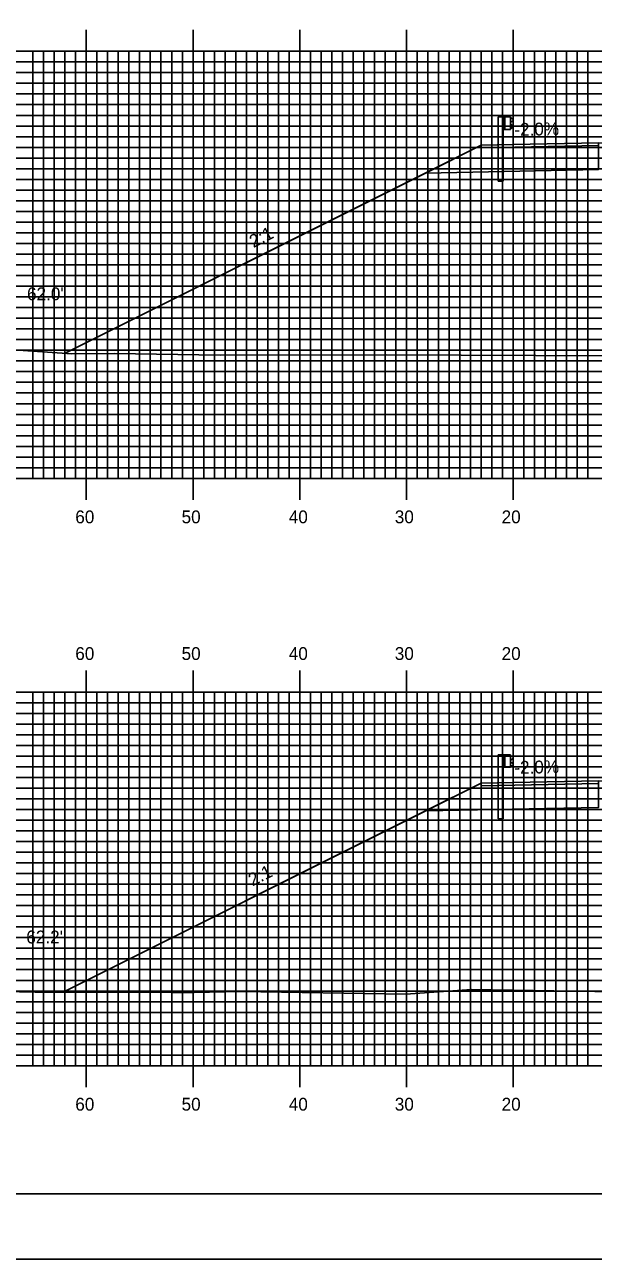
# Model space of a CAD drawing. Extents: x 1812161 to 1812504, y 442591 to 442811.
# Drawn here: x 1812260.7 to 1812313.9, y 442590.5 to 442706.2 of the extents above; entities that cross this region are included whole.
import ezdxf

# ---------------------------------------------------------------- set-up
doc = ezdxf.new("R2010")
doc.units = 0
for name, color, linetype in [('ANNOTATION', 7, 'Continuous'), ('BORDER', 7, 'Continuous'), ('D_Guardrail_Beam_Lt', 7, 'Continuous'), ('D_Roadway_Centerline', 7, 'Continuous'), ('D_Roadway_Edge_Shoulder', 7, 'Continuous'), ('D_Roadway_SlopeLines', 7, 'Continuous'), ('D_Roadway_SubGrade', 7, 'Continuous'), ('D_Text_Standard', 7, 'Continuous'), ('H_V ANNOTATION', 7, 'Continuous'), ('MAJOR', 7, 'Continuous'), ('MINOR', 7, 'Continuous'), ('PLOT BOUNDARY', 7, 'Continuous'), ('S_Roadway_Centerline', 7, 'Continuous')]:
    doc.layers.add(name, color=color, linetype=linetype)

msp = doc.modelspace()

# ---------------------------------------------------------------- linework, layer by layer
at = {"layer": 'BORDER'}
msp.add_lwpolyline([(1812176.83, 442596.67), (1812496.83, 442596.67), (1812496.83, 442806.67), (1812176.83, 442806.67)], close=True, dxfattribs=at)
at = {"layer": 'D_Guardrail_Beam_Lt'}
for p, q in [((1812305, 442697.52), (1812305, 442691.52)), ((1812305.47, 442697.52), (1812305, 442697.52)), ((1812306.16, 442697.52), (1812305.47, 442697.52)), ((1812305.47, 442697.52), (1812305.47, 442696.35)), ((1812305.53, 442697.52), (1812305.53, 442696.35)), ((1812305.64, 442697.52), (1812305.64, 442696.35)), ((1812306.16, 442696.35), (1812306.16, 442697.52)), ((1812306.16, 442697.44), (1812306.23, 442697.42)), ((1812306.39, 442697.17), (1812306.2, 442697.04)), ((1812306.25, 442697.41), (1812306.39, 442697.31)), ((1812305.47, 442696.35), (1812306.16, 442696.35)), ((1812305.49, 442691.52), (1812305.49, 442696.35)), ((1812306.16, 442696.97), (1812306.16, 442696.9)), ((1812306.23, 442696.45), (1812306.16, 442696.44)), ((1812306.2, 442696.84), (1812306.39, 442696.7)), ((1812306.39, 442696.56), (1812306.25, 442696.46)), ((1812305.49, 442691.52), (1812305, 442691.52)), ((1812305, 442637.78), (1812305, 442631.78)), ((1812305.47, 442637.78), (1812305, 442637.78)), ((1812306.16, 442637.78), (1812305.47, 442637.78)), ((1812305.47, 442637.78), (1812305.47, 442636.62)), ((1812305.53, 442637.78), (1812305.53, 442636.62)), ((1812305.64, 442637.78), (1812305.64, 442636.62)), ((1812306.16, 442636.62), (1812306.16, 442637.78)), ((1812306.16, 442637.7), (1812306.23, 442637.68)), ((1812306.16, 442637.23), (1812306.16, 442637.16)), ((1812306.39, 442637.43), (1812306.2, 442637.3)), ((1812306.2, 442637.1), (1812306.39, 442636.96)), ((1812306.25, 442637.68), (1812306.39, 442637.58)), ((1812305.47, 442636.62), (1812306.16, 442636.62)), ((1812305.49, 442631.78), (1812305.49, 442636.62)), ((1812306.23, 442636.71), (1812306.16, 442636.7)), ((1812306.39, 442636.82), (1812306.25, 442636.72)), ((1812305.49, 442631.78), (1812305, 442631.78))]:
    msp.add_line(p, q, dxfattribs=at)
for centre, major_axis, start_param, end_param in [((1812306.22, 442697.38), (0.0417, 0), 0.959931, 1.376053), ((1812306.34, 442697.24), (0.0877, 0), 5.323254, 7.243116), ((1812306.24, 442696.97), (-0.0789, 0), 5.323254, 6.283185), ((1812306.24, 442696.9), (-0.0789, 0), 6.283185, 7.243116), ((1812306.22, 442696.49), (0.0417, 0), 4.907132, 5.323254), ((1812306.34, 442696.63), (0.0877, 0), 5.323254, 7.243116), ((1812306.24, 442637.23), (-0.0789, 0), 5.323254, 6.283185), ((1812306.24, 442637.16), (-0.0789, 0), 6.283185, 7.243116), ((1812306.22, 442637.64), (0.0417, 0), 0.959931, 1.376053), ((1812306.34, 442637.51), (0.0877, 0), 5.323254, 7.243116), ((1812306.22, 442636.75), (0.0417, 0), 4.907132, 5.323254), ((1812306.34, 442636.89), (0.0877, 0), 5.323254, 7.243116)]:
    msp.add_ellipse(centre, major_axis=major_axis, ratio=0.995501, start_param=start_param, end_param=end_param, dxfattribs=at)
at = {"layer": 'D_Roadway_Centerline'}
for points in [[(1812264.46, 442675.39), (1812298.22, 442692.27), (1812303.43, 442694.88), (1812306.43, 442694.94), (1812314.43, 442695.1), (1812326.43, 442694.52), (1812338.43, 442693.94), (1812346.43, 442693.56), (1812349.43, 442693.42), (1812354.96, 442690.65), (1812388.17, 442674.04)], [(1812264.27, 442615.56), (1812298.22, 442632.53), (1812303.43, 442635.14), (1812306.43, 442635.2), (1812314.43, 442635.36), (1812326.43, 442634.78), (1812338.43, 442634.21), (1812346.43, 442633.82), (1812349.43, 442633.68), (1812354.96, 442630.91), (1812387.04, 442614.87)]]:
    msp.add_lwpolyline(points, dxfattribs=at)
at = {"layer": 'D_Roadway_Edge_Shoulder'}
for points in [[(1812314.43, 442695.1), (1812306.43, 442694.94), (1812306.43, 442694.94), (1812303.43, 442694.88), (1812303.43, 442694.63), (1812314.43, 442694.85)], [(1812314.43, 442635.36), (1812306.43, 442635.2), (1812306.43, 442635.2), (1812303.43, 442635.14), (1812303.43, 442634.89), (1812314.43, 442635.11)]]:
    msp.add_lwpolyline(points, close=True, dxfattribs=at)
at = {"layer": 'D_Roadway_SlopeLines'}
for points in [[(1812303.43, 442694.88), (1812264.46, 442675.39)], [(1812303.43, 442635.14), (1812264.27, 442615.56)]]:
    msp.add_lwpolyline(points, dxfattribs=at)
at = {"layer": 'D_Roadway_SubGrade'}
for points in [[(1812314.43, 442694.43), (1812314.43, 442694.85), (1812303.43, 442694.63), (1812303.43, 442694.88), (1812298.22, 442692.27), (1812314.43, 442692.6)], [(1812314.43, 442634.69), (1812314.43, 442635.11), (1812303.43, 442634.89), (1812303.43, 442635.14), (1812298.22, 442632.53), (1812314.43, 442632.86)]]:
    msp.add_lwpolyline(points, close=True, dxfattribs=at)
at = {"layer": 'MAJOR'}
for p, q in [((1812266.43, 442705.67), (1812266.43, 442703.67)), ((1812276.43, 442705.67), (1812276.43, 442703.67)), ((1812286.43, 442705.67), (1812286.43, 442703.67)), ((1812296.43, 442705.67), (1812296.43, 442703.67)), ((1812306.43, 442705.67), (1812306.43, 442703.67)), ((1812186.43, 442703.67), (1812466.43, 442703.67)), ((1812186.43, 442703.67), (1812466.43, 442703.67)), ((1812266.43, 442663.67), (1812266.43, 442703.67)), ((1812276.43, 442663.67), (1812276.43, 442703.67)), ((1812286.43, 442663.67), (1812286.43, 442703.67)), ((1812296.43, 442663.67), (1812296.43, 442703.67)), ((1812306.43, 442663.67), (1812306.43, 442703.67)), ((1812186.43, 442698.67), (1812466.43, 442698.67)), ((1812186.43, 442693.67), (1812466.43, 442693.67)), ((1812186.43, 442688.67), (1812466.43, 442688.67)), ((1812186.43, 442683.67), (1812466.43, 442683.67)), ((1812186.43, 442678.67), (1812466.43, 442678.67)), ((1812186.43, 442673.67), (1812466.43, 442673.67)), ((1812186.43, 442668.67), (1812466.43, 442668.67)), ((1812186.43, 442663.67), (1812466.43, 442663.67)), ((1812186.43, 442663.67), (1812466.43, 442663.67)), ((1812266.43, 442661.66), (1812266.43, 442663.67)), ((1812276.43, 442661.66), (1812276.43, 442663.67)), ((1812286.43, 442661.66), (1812286.43, 442663.67)), ((1812296.43, 442661.66), (1812296.43, 442663.67)), ((1812306.43, 442661.66), (1812306.43, 442663.67)), ((1812266.43, 442645.67), (1812266.43, 442643.67)), ((1812276.43, 442645.67), (1812276.43, 442643.67)), ((1812286.43, 442645.67), (1812286.43, 442643.67)), ((1812296.43, 442645.67), (1812296.43, 442643.67)), ((1812306.43, 442645.67), (1812306.43, 442643.67)), ((1812186.43, 442643.67), (1812466.43, 442643.67)), ((1812186.43, 442643.67), (1812466.43, 442643.67)), ((1812266.43, 442608.67), (1812266.43, 442643.67)), ((1812276.43, 442608.67), (1812276.43, 442643.67)), ((1812286.43, 442608.67), (1812286.43, 442643.67)), ((1812296.43, 442608.67), (1812296.43, 442643.67)), ((1812306.43, 442608.67), (1812306.43, 442643.67)), ((1812186.43, 442638.67), (1812466.43, 442638.67)), ((1812186.43, 442633.67), (1812466.43, 442633.67)), ((1812186.43, 442628.67), (1812466.43, 442628.67)), ((1812186.43, 442623.67), (1812466.43, 442623.67)), ((1812186.43, 442618.67), (1812466.43, 442618.67)), ((1812186.43, 442613.67), (1812466.43, 442613.67)), ((1812186.43, 442608.67), (1812466.43, 442608.67)), ((1812186.43, 442608.67), (1812466.43, 442608.67)), ((1812266.43, 442606.66), (1812266.43, 442608.67)), ((1812276.43, 442606.66), (1812276.43, 442608.67)), ((1812286.43, 442606.66), (1812286.43, 442608.67)), ((1812296.43, 442606.66), (1812296.43, 442608.67)), ((1812306.43, 442606.66), (1812306.43, 442608.67))]:
    msp.add_line(p, q, dxfattribs=at)
at = {"layer": 'MINOR'}
for p, q in [((1812261.43, 442663.67), (1812261.43, 442703.67)), ((1812262.43, 442663.67), (1812262.43, 442703.67)), ((1812263.43, 442663.67), (1812263.43, 442703.67)), ((1812264.43, 442663.67), (1812264.43, 442703.67)), ((1812265.43, 442663.67), (1812265.43, 442703.67)), ((1812267.43, 442663.67), (1812267.43, 442703.67)), ((1812268.43, 442663.67), (1812268.43, 442703.67)), ((1812269.43, 442663.67), (1812269.43, 442703.67)), ((1812270.43, 442663.67), (1812270.43, 442703.67)), ((1812271.43, 442663.67), (1812271.43, 442703.67)), ((1812272.43, 442663.67), (1812272.43, 442703.67)), ((1812273.43, 442663.67), (1812273.43, 442703.67)), ((1812274.43, 442663.67), (1812274.43, 442703.67)), ((1812275.43, 442663.67), (1812275.43, 442703.67)), ((1812277.43, 442663.67), (1812277.43, 442703.67)), ((1812278.43, 442663.67), (1812278.43, 442703.67)), ((1812279.43, 442663.67), (1812279.43, 442703.67)), ((1812280.43, 442663.67), (1812280.43, 442703.67)), ((1812281.43, 442663.67), (1812281.43, 442703.67)), ((1812282.43, 442663.67), (1812282.43, 442703.67)), ((1812283.43, 442663.67), (1812283.43, 442703.67)), ((1812284.43, 442663.67), (1812284.43, 442703.67)), ((1812285.43, 442663.67), (1812285.43, 442703.67)), ((1812287.43, 442663.67), (1812287.43, 442703.67)), ((1812288.43, 442663.67), (1812288.43, 442703.67)), ((1812289.43, 442663.67), (1812289.43, 442703.67)), ((1812290.43, 442663.67), (1812290.43, 442703.67)), ((1812291.43, 442663.67), (1812291.43, 442703.67)), ((1812292.43, 442663.67), (1812292.43, 442703.67)), ((1812293.43, 442663.67), (1812293.43, 442703.67)), ((1812294.43, 442663.67), (1812294.43, 442703.67)), ((1812295.43, 442663.67), (1812295.43, 442703.67)), ((1812297.43, 442663.67), (1812297.43, 442703.67)), ((1812298.43, 442663.67), (1812298.43, 442703.67)), ((1812299.43, 442663.67), (1812299.43, 442703.67)), ((1812300.43, 442663.67), (1812300.43, 442703.67)), ((1812301.43, 442663.67), (1812301.43, 442703.67)), ((1812302.43, 442663.67), (1812302.43, 442703.67)), ((1812303.43, 442663.67), (1812303.43, 442703.67)), ((1812304.43, 442663.67), (1812304.43, 442703.67)), ((1812305.43, 442663.67), (1812305.43, 442703.67)), ((1812307.43, 442663.67), (1812307.43, 442703.67)), ((1812308.43, 442663.67), (1812308.43, 442703.67)), ((1812309.43, 442663.67), (1812309.43, 442703.67)), ((1812310.43, 442663.67), (1812310.43, 442703.67)), ((1812311.43, 442663.67), (1812311.43, 442703.67)), ((1812312.43, 442663.67), (1812312.43, 442703.67)), ((1812313.43, 442663.67), (1812313.43, 442703.67)), ((1812186.43, 442702.67), (1812466.43, 442702.67)), ((1812186.43, 442701.67), (1812466.43, 442701.67)), ((1812186.43, 442700.67), (1812466.43, 442700.67)), ((1812186.43, 442699.67), (1812466.43, 442699.67)), ((1812186.43, 442697.67), (1812466.43, 442697.67)), ((1812186.43, 442696.67), (1812466.43, 442696.67)), ((1812186.43, 442695.67), (1812466.43, 442695.67)), ((1812186.43, 442694.67), (1812466.43, 442694.67)), ((1812186.43, 442692.67), (1812466.43, 442692.67)), ((1812186.43, 442691.67), (1812466.43, 442691.67)), ((1812186.43, 442690.67), (1812466.43, 442690.67)), ((1812186.43, 442689.67), (1812466.43, 442689.67)), ((1812186.43, 442687.67), (1812466.43, 442687.67)), ((1812186.43, 442686.67), (1812466.43, 442686.67)), ((1812186.43, 442685.67), (1812466.43, 442685.67)), ((1812186.43, 442684.67), (1812466.43, 442684.67)), ((1812186.43, 442682.67), (1812466.43, 442682.67)), ((1812186.43, 442681.67), (1812466.43, 442681.67)), ((1812186.43, 442680.67), (1812466.43, 442680.67)), ((1812186.43, 442679.67), (1812466.43, 442679.67)), ((1812186.43, 442677.67), (1812466.43, 442677.67)), ((1812186.43, 442676.67), (1812466.43, 442676.67)), ((1812186.43, 442675.67), (1812466.43, 442675.67)), ((1812186.43, 442674.67), (1812466.43, 442674.67)), ((1812186.43, 442672.67), (1812466.43, 442672.67)), ((1812186.43, 442671.67), (1812466.43, 442671.67)), ((1812186.43, 442670.67), (1812466.43, 442670.67)), ((1812186.43, 442669.67), (1812466.43, 442669.67)), ((1812186.43, 442667.67), (1812466.43, 442667.67)), ((1812186.43, 442666.67), (1812466.43, 442666.67)), ((1812186.43, 442665.67), (1812466.43, 442665.67)), ((1812186.43, 442664.67), (1812466.43, 442664.67)), ((1812261.43, 442608.67), (1812261.43, 442643.67)), ((1812262.43, 442608.67), (1812262.43, 442643.67)), ((1812263.43, 442608.67), (1812263.43, 442643.67)), ((1812264.43, 442608.67), (1812264.43, 442643.67)), ((1812265.43, 442608.67), (1812265.43, 442643.67)), ((1812267.43, 442608.67), (1812267.43, 442643.67)), ((1812268.43, 442608.67), (1812268.43, 442643.67)), ((1812269.43, 442608.67), (1812269.43, 442643.67)), ((1812270.43, 442608.67), (1812270.43, 442643.67)), ((1812271.43, 442608.67), (1812271.43, 442643.67)), ((1812272.43, 442608.67), (1812272.43, 442643.67)), ((1812273.43, 442608.67), (1812273.43, 442643.67)), ((1812274.43, 442608.67), (1812274.43, 442643.67)), ((1812275.43, 442608.67), (1812275.43, 442643.67)), ((1812277.43, 442608.67), (1812277.43, 442643.67)), ((1812278.43, 442608.67), (1812278.43, 442643.67)), ((1812279.43, 442608.67), (1812279.43, 442643.67)), ((1812280.43, 442608.67), (1812280.43, 442643.67)), ((1812281.43, 442608.67), (1812281.43, 442643.67)), ((1812282.43, 442608.67), (1812282.43, 442643.67)), ((1812283.43, 442608.67), (1812283.43, 442643.67)), ((1812284.43, 442608.67), (1812284.43, 442643.67)), ((1812285.43, 442608.67), (1812285.43, 442643.67)), ((1812287.43, 442608.67), (1812287.43, 442643.67)), ((1812288.43, 442608.67), (1812288.43, 442643.67)), ((1812289.43, 442608.67), (1812289.43, 442643.67)), ((1812290.43, 442608.67), (1812290.43, 442643.67)), ((1812291.43, 442608.67), (1812291.43, 442643.67)), ((1812292.43, 442608.67), (1812292.43, 442643.67)), ((1812293.43, 442608.67), (1812293.43, 442643.67)), ((1812294.43, 442608.67), (1812294.43, 442643.67)), ((1812295.43, 442608.67), (1812295.43, 442643.67)), ((1812297.43, 442608.67), (1812297.43, 442643.67)), ((1812298.43, 442608.67), (1812298.43, 442643.67)), ((1812299.43, 442608.67), (1812299.43, 442643.67)), ((1812300.43, 442608.67), (1812300.43, 442643.67)), ((1812301.43, 442608.67), (1812301.43, 442643.67)), ((1812302.43, 442608.67), (1812302.43, 442643.67)), ((1812303.43, 442608.67), (1812303.43, 442643.67)), ((1812304.43, 442608.67), (1812304.43, 442643.67)), ((1812305.43, 442608.67), (1812305.43, 442643.67)), ((1812307.43, 442608.67), (1812307.43, 442643.67)), ((1812308.43, 442608.67), (1812308.43, 442643.67)), ((1812309.43, 442608.67), (1812309.43, 442643.67)), ((1812310.43, 442608.67), (1812310.43, 442643.67)), ((1812311.43, 442608.67), (1812311.43, 442643.67)), ((1812312.43, 442608.67), (1812312.43, 442643.67)), ((1812313.43, 442608.67), (1812313.43, 442643.67)), ((1812186.43, 442642.67), (1812466.43, 442642.67)), ((1812186.43, 442641.67), (1812466.43, 442641.67)), ((1812186.43, 442640.67), (1812466.43, 442640.67)), ((1812186.43, 442639.67), (1812466.43, 442639.67)), ((1812186.43, 442637.67), (1812466.43, 442637.67)), ((1812186.43, 442636.67), (1812466.43, 442636.67)), ((1812186.43, 442635.67), (1812466.43, 442635.67)), ((1812186.43, 442634.67), (1812466.43, 442634.67)), ((1812186.43, 442632.67), (1812466.43, 442632.67)), ((1812186.43, 442631.67), (1812466.43, 442631.67)), ((1812186.43, 442630.67), (1812466.43, 442630.67)), ((1812186.43, 442629.67), (1812466.43, 442629.67)), ((1812186.43, 442627.67), (1812466.43, 442627.67)), ((1812186.43, 442626.67), (1812466.43, 442626.67)), ((1812186.43, 442625.67), (1812466.43, 442625.67)), ((1812186.43, 442624.67), (1812466.43, 442624.67)), ((1812186.43, 442622.67), (1812466.43, 442622.67)), ((1812186.43, 442621.67), (1812466.43, 442621.67)), ((1812186.43, 442620.67), (1812466.43, 442620.67)), ((1812186.43, 442619.67), (1812466.43, 442619.67)), ((1812186.43, 442617.67), (1812466.43, 442617.67)), ((1812186.43, 442616.67), (1812466.43, 442616.67)), ((1812186.43, 442615.67), (1812466.43, 442615.67)), ((1812186.43, 442614.67), (1812466.43, 442614.67)), ((1812186.43, 442612.67), (1812466.43, 442612.67)), ((1812186.43, 442611.67), (1812466.43, 442611.67)), ((1812186.43, 442610.67), (1812466.43, 442610.67)), ((1812186.43, 442609.67), (1812466.43, 442609.67))]:
    msp.add_line(p, q, dxfattribs=at)
at = {"layer": 'PLOT BOUNDARY'}
msp.add_lwpolyline([(1812160.64, 442590.55), (1812500.64, 442590.55), (1812500.64, 442810.55), (1812160.64, 442810.55)], close=True, dxfattribs=at)
at = {"layer": 'S_Roadway_Centerline'}
for points in [[(1812186.43, 442674.96), (1812193.49, 442674.87), (1812194.41, 442674.88), (1812195.23, 442674.88), (1812210.71, 442676.18), (1812219.13, 442675.79), (1812230.64, 442676.24), (1812243.89, 442676.54), (1812246.7, 442676.6), (1812257.26, 442675.86), (1812265.07, 442675.35), (1812269.05, 442675.38), (1812278.98, 442675.22), (1812294.55, 442675.24), (1812315.55, 442675.14), (1812318.24, 442675.16), (1812319.32, 442675.14), (1812336.42, 442674.72), (1812344.7, 442674.69), (1812354.49, 442674.44), (1812363.29, 442674.11), (1812371.95, 442674.39), (1812382.38, 442674.43), (1812389.75, 442673.94)], [(1812248.45, 442615.83), (1812261.63, 442615.57), (1812274.45, 442615.53), (1812276.55, 442615.54), (1812280.86, 442615.61), (1812296.38, 442615.39), (1812302.51, 442615.82), (1812314.06, 442615.61), (1812326.73, 442615.27), (1812332.08, 442615.07), (1812338.22, 442614.92), (1812354.27, 442614.92), (1812364.46, 442614.86), (1812368.1, 442614.86), (1812377.02, 442614.84), (1812386.61, 442614.87), (1812389.66, 442614.89)]]:
    msp.add_lwpolyline(points, dxfattribs=at)

# ---------------------------------------------------------------- texts
at = {"layer": 'ANNOTATION'}
for s, rotation, p in [('-2.0%', 1.1458, (1812306.54, 442695.74)), ('2:1', 26.5651, (1812282.09, 442685.24)), ('-2.0%', 1.1458, (1812306.54, 442636)), ('2:1', 26.5651, (1812281.99, 442625.46))]:
    msp.add_text(s, height=1.2, rotation=rotation, dxfattribs=at).set_placement(p)
at = {"layer": 'D_Text_Standard'}
for s, p in [("62.0'", (1812260.88, 442680.36)), ("62.2'", (1812260.81, 442620.13))]:
    msp.add_text(s, height=1.2, dxfattribs=at).set_placement(p)
at = {"layer": 'H_V ANNOTATION'}
for s, p in [('60', (1812265.4, 442659.47)), ('50', (1812275.36, 442659.47)), ('40', (1812285.4, 442659.47)), ('30', (1812295.33, 442659.47)), ('20', (1812305.34, 442659.47)), ('60', (1812265.4, 442646.67)), ('50', (1812275.36, 442646.67)), ('40', (1812285.4, 442646.67)), ('30', (1812295.33, 442646.67)), ('20', (1812305.34, 442646.67)), ('60', (1812265.4, 442604.47)), ('50', (1812275.36, 442604.47)), ('40', (1812285.4, 442604.47)), ('30', (1812295.33, 442604.47)), ('20', (1812305.34, 442604.47))]:
    msp.add_text(s, height=1.2, dxfattribs=at).set_placement(p)

doc.saveas('drawing.dxf')
